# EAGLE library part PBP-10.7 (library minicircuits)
Band Pass Filter Source: minicircuits.com .. PBP-10.7+.pdf
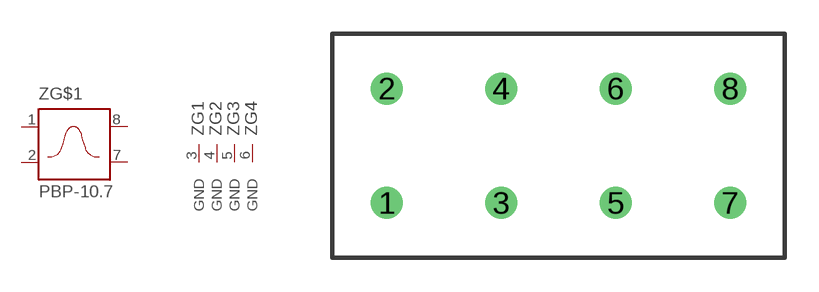
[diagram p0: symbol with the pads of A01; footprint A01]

Designator prefix Z; gates G$1=BANDPASS G1=GROUND G2=GROUND G3=GROUND G4=GROUND

## PBP-10.7 (OC_FARNELL: unknown; OC_NEWARK: unknown)  [A01]
1  G$1:IN  in
2  G$1:GND  in
3  G1:GND  pwr
4  G2:GND  pwr
5  G3:GND  pwr
6  G4:GND  pwr
7  G$1:GND  in
8  G$1:OUT  in

## Footprint A01 (pad centres in mm)
CASE STYLE A01 Source: minicircuits.com .. PBP-10.7+.pdf
drill 0.9 pad 1.422 round: 1 -7.62,-2.54; 2 -7.62,2.54; 3 -2.54,-2.54; 4 -2.54,2.54; 5 2.54,-2.54; 6 2.54,2.54; 7 7.62,-2.54; 8 7.62,2.54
